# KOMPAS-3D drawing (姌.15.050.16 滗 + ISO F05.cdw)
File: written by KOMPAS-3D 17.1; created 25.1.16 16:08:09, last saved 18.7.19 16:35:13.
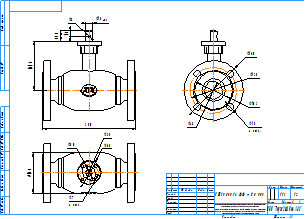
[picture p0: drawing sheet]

Sheet 1: A3, landscape

Title block, sheet 1: name: КШ.15.050.16 ФФ + ISO F05; mass: 11,3; sheets: 1; organisation: ООО "Торговый дом АДЛ"; sheet format: A3; stored path: C:\Users\kka\KOMPAS_Work\Модели кранов для исследований\DN65\КШГХ.15.50.16 ФФ ГЧ _ Шаровой кран БИВАЛ Ду50 Ру1,6 МПа  полнопроходной хладостойкий фланцевый Габаритный чертеж.cdw

Views: Вид 1, Проекционный вид 2, Проекционный вид 3
Referenced files in C:\Users\kka\KOMPAS_Work\Модели кранов для исследований\DN65\: КШ.15.050.16 фф + ISO F05.m3d
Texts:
  Klimkovich
  ADL
  Рама для чертежей
  Лит-Масса-Масштаб
  Материал-Предприятие
  Масштаб
  Изм.
  Лист
  № докум.
  Подп.
  Дата
  Лит.
  Разраб.
  Пров.
  Т.контр.
  Листов
  Внимание! Данный продукт является объектом авторского права ООО «Торговый Дом АДЛ».
  Запрещается изменение, копирование, распространение
  (в том числе путем копирования на другие сайты и ресурсы в Интернете)
  или любое иное использование информации и объектов без предварительного
  согласия правообладателя (ООО «Торговый Дом АДЛ»).
  Н.контр.
  Утв.
  Изменение
  Номер документа
  Подпись
  Обозначение документа
  Наименование изделия
  Масса изделия по ГОСТ 2.109-73
  Порядковый номер листа
  Общее количество листов в документе
  Характер работы, выполненной лицом, подписавшим документ
  Наименование или индекс предприятия, выпускающего документ
  Инв. № подл.
  Подп. и дата
  Взам. инв. №
  Инв. № дубл.
  Инвентарный номер подлинника по ГОСТ 2.501-68
  Подпись принявшего подлинник в отдел технической документации
  Инвентарный номер подлинника, взамен которого выпущен данный подлинник
  Инвентарный номер дубликата по ГОСТ 2.502-68
  Подпись принявшего дубликат в отдел технической документации
  Справ. №
  Перв. примен.
  Обозначение документа, взамен или на основании которого выпущен данный документ
  Обозначение документа, в котором впервые записан данный документ
  Подпись лица, копировавшего чертеж
  Обозначение формата листа
  !Рама для чертежа
Dimensions and other numbers on the sheet: 250; 131,8; 27,5; 15; 18; 8; 160; 125; 102; 4 отв.; 48; 108; 65; 50; 7; 35; 1:2; 1; 11,3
